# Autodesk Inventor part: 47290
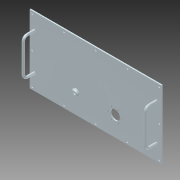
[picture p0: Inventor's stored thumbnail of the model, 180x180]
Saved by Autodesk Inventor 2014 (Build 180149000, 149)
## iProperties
Shininess: 20.0
Length Units: 11272
Angle Units: 11279
Time Units: 11290
Mass Units: 11286
Length Display Precision: 3
Angle Display Precision: 2
Company: Autodesk, Inc.
Created: 2002-06
Part Number: 47290
Material: Stainless Steel 316
Description: COVER WLDMT,TANK;*B; 100GL (SS)
Document SubType Name: Modeling
Designer: Autodesk, Inc.
Density: 8.182 g/cm^3
Mass: 13142.6 g
Surface Area: 5227.28 cm^2
Volume: 1606.28 cm^3
Appearance: Stainless Steel
Density: 0.0
Volumn: 0.0
Area: 0.0
PropertySet Name: Model Information
Control State: 0
Master: False
Checked Out: False
Last Check In By: JT
Last Check In Date: 2003-06-20
Title: COVER WLDMT,TANK;*B; 100GL (SS)
Author: Autodesk, Inc.
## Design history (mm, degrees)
derived "47290.iam"
  feature "47291.ipt:1" dims "d3" = 10
  feature "243107.ipt:1" dims "d3" = 10
  feature "47292.ipt:1" dims "d3" = 10
  feature "47292.ipt:2" dims "d3" = 10
body "Solid1"
